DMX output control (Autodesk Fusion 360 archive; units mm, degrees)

design "case" references "3-D NC5FAH", "ptb6043-2010bp", "nac3mpxxa", "xiaodmx", "5V2AACDC"
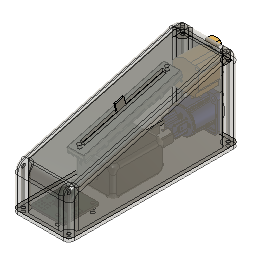
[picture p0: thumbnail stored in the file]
sketch "Sketch1" plane through (0, 0, 0) normal (0, 0, 1) x axis (1, 0, 0)
  line L1 (-25.2326, 75) -> (24.7674, 75)
  line L2 (-25.2326, -75) -> (-25.2326, 75)
  line L3 (24.7674, -75) -> (-25.2326, -75)
  line L4 (24.7674, 75) -> (24.7674, -75)
  line L5 (-25.2326, -75) -> (24.7674, 75)
  line L6 (24.7674, -75) -> (-25.2326, 75)
  point P6 (-0.2326, 0)
  point P4 (-25.2326, -75)
  point P5 (24.7674, -75)
  point P3 (-25.2326, 75)
  horizontal L1
  perpendicular L1 L2
  parallel L1 L3
  parallel L2 L4
  coincident L5 P6
  coincident L6 P6
  dimension "d1" distance P4 P5 = 50
  dimension "d2" distance P3 P4 = 150
extrude "Extrude1" new body sketch "Sketch1" profile of L1 L2 L3 L4 along normal blind 75
chamfer "Chamfer1" distance 150 Rotate Angle 15
fillet "Fillet1" radius 10 10
fillet "Fillet2" radius 5
sketch "Sketch2" plane through (0, -13.726, 51.226) normal (0, -0.2588, 0.9659) x axis (1, 0, 0)
  line L1 (19.7674, 78.8236) -> (19.7674, -55.7623)
  line L2 (-20.2326, 78.8236) -> (19.7674, 78.8236)
  line L3 (-20.2326, -55.7623) -> (-20.2326, 78.8236)
  line L4 (19.7674, -55.7623) -> (-20.2326, -55.7623)
  line L5 (19.7674, -55.7623) -> (-20.2326, 78.8236)
  line L6 (-20.2326, -55.7623) -> (19.7674, 78.8236)
  point P4 (-20.2326, 78.8236)
  point P6 (-20.2326, 78.8236)
  point P2 (19.7674, -55.7623)
  point P7 (19.7674, -55.7623)
  point P3 (19.7674, 78.8236)
  point P8 (19.7674, 78.8236)
  point P5 (-20.2326, -55.7623)
  point P9 (-20.2326, -55.7623)
  point P10 (-0.2326, 11.5307)
  coincident P4 P6
  coincident P2 P7
  coincident P3 P8
  coincident P5 P9
  midpoint L6 P10
shell "Shell1" innerThickness 3
component_from_bodies "ボディ -> コンポーネント"
component_insert "Component Insert1"
joint "Assemble" alignAngle 90 alignOffsetX 0 alignOffsetY 0 alignOffsetZ 0
sketch "Sketch3" plane through (0.2736, -1.8193, 51.3105) normal (0, -0.2588, 0.9659) x axis (-1, 0, 0)
  line L1 (-6.3438, -43.7578) -> (-6.3438, -43.5578)
  line L2 (7.3562, -43.7578) -> (-6.3438, -43.7578)
  line L3 (7.3562, -43.5578) -> (7.3562, -43.7578)
  line L4 (7.5562, -43.5578) -> (7.3562, -43.5578)
  line L5 (7.5562, 43.5422) -> (7.5562, -43.5578)
  line L6 (7.3562, 43.5422) -> (7.5562, 43.5422)
  line L7 (7.3562, 43.7422) -> (7.3562, 43.5422)
  line L8 (-6.3438, 43.7422) -> (7.3562, 43.7422)
  line L9 (-6.3438, 43.5422) -> (-6.3438, 43.7422)
  line L10 (-6.5438, 43.5422) -> (-6.3438, 43.5422)
  line L11 (-6.5438, -43.5578) -> (-6.5438, 43.5422)
  line L12 (-6.3438, -43.5578) -> (-6.5438, -43.5578)
  line L13 (-0.9188, -37.0078) -> (1.9312, -37.0078)
  line L14 (-0.9188, 36.9922) -> (-0.9188, -37.0078)
  line L15 (1.9312, 36.9922) -> (-0.9188, 36.9922)
  line L16 (1.9312, -37.0078) -> (1.9312, 36.9922)
  line L17 (1.9312, -37.0078) -> (-0.9188, 36.9922)
  line L18 (-0.9188, -37.0078) -> (1.9312, 36.9922)
  line L19 (-0.9188, -37.0078) -> (1.9312, -37.0078)
  line L20 (-0.9188, 36.9922) -> (1.9312, 36.9922)
  line L21 (-0.9188, -37.0078) -> (-0.9188, 36.9922)
  line L22 (1.9312, 36.9922) -> (1.9312, -37.0078)
  circle C1 centre (0.5062, -40.0078) radius 1.25
  circle C2 centre (0.5062, 39.9922) radius 1.25
  circle C3 centre (0.5062, -40.0078) radius 1.5
  circle C4 centre (0.5062, 39.9922) radius 1.5
  point P18 (-0.9188, 36.9922)
  point P20 (-0.9188, 36.9922)
  point P16 (1.9312, -37.0078)
  point P21 (1.9312, -37.0078)
  point P19 (1.9312, 36.9922)
  point P22 (1.9312, 36.9922)
  point P17 (-0.9188, -37.0078)
  point P23 (-0.9188, -37.0078)
  point P24 (0.5062, -0.0078)
  coincident P18 P20
  coincident P16 P21
  coincident P19 P22
  coincident P17 P23
  coincident L18 P24
  coincident L17 P24
  concentric C1 C3
  concentric C2 C4
  dimension "d22" diameter C3 = 3
  dimension "d23" diameter C4 = 3
extrude "Extrude1" cut sketch "Sketch3" profile of C1 C2 L13 L14 L15 L16 L17 L18 L19 L20 L21 L22 C3 C4 along normal blind 10
component_insert "Component Insert2"
step "GeometricRelationship1"
step "GeometricRelationship2" Offset 0
component_insert "Component Insert3"
step "GeometricRelationship3"
step "GeometricRelationship4" Offset 0
position "Position1"
sketch "Sketch6" plane through (0, 66.1549, 0) normal (0, -1, 0) x axis (1, 0, 0)
  line L1 (31, -12.7756) -> (-9, -12.7756)
  line L2 (31, 49.1922) -> (31, -12.7756)
  line L3 (-9, 49.1922) -> (31, 49.1922)
  line L4 (-9, -12.7756) -> (-9, 49.1922)
  circle C1 centre (11, 3.8312) radius 12
  circle C2 centre (11, 3.8312) radius 11.509
  circle C3 centre (20.5, 15.8312) radius 1.5
  circle C4 centre (20.5, 15.8312) radius 1.7227
  circle C5 centre (1.5, -8.1688) radius 1.5
  circle C6 centre (1.5, -8.1688) radius 1.7227
  circle C7 centre (11, 36.1664) radius 11.1
  arc A1 centre (11, 36.1664) radius 9.75 clockwise from (13.5, 45.5904) to (8.5, 45.5904)
  circle C8 centre (20.9, 46.0664) radius 1.5
  circle C9 centre (20.9, 46.0664) radius 1.175
  circle C10 centre (1.1, 26.2664) radius 1.5
  circle C11 centre (1.1, 26.2664) radius 1.175
  concentric C1 C2
  concentric C3 C4
  concentric C5 C6
  concentric C7 A1
  concentric C8 C9
  concentric C10 C11
  dimension "d28" diameter C1 = 24
  dimension "d29" diameter C3 = 3
  dimension "d30" diameter C5 = 3
  dimension "d31" diameter C7 = 22.2
  dimension "d32" diameter C8 = 3
  dimension "d33" diameter C10 = 3
extrude "Extrude2" cut sketch "Sketch6" profile of C1 C2 C3 C5 C7 C8 C9 C10 C11 against normal blind 60
sketch "Sketch7" plane through (0, 0, -12.7756) normal (0, 0, -1) x axis (1, 0, 0)
  line L1 (33, -64.1549) -> (33, 75.8451)
  line L2 (-9, -66.1549) -> (31, -66.1549)
  line L3 (-11, 75.8451) -> (-11, -64.1549)
  line L4 (31, 77.8451) -> (-9, 77.8451)
  line L5 (36, 75.8451) -> (36, -64.1549)
  line L6 (-9, 80.8451) -> (31, 80.8451)
  line L7 (-14, -64.1549) -> (-14, 75.8451)
  line L8 (31, -69.1549) -> (-9, -69.1549)
  line L9 (-9, 75.8451) -> (-12.5355, 79.3806)
  line L10 (31, 75.8451) -> (34.5355, 79.3806)
  line L11 (31, -64.1549) -> (34.5355, -67.6905)
  line L12 (-9, -64.1549) -> (-12.5355, -67.6905)
  arc A1 centre (31, -64.1549) radius 2 clockwise from (33, -64.1549) to (31, -66.1549)
  arc A2 centre (-9, -64.1549) radius 2 clockwise from (-9, -66.1549) to (-11, -64.1549)
  arc A3 centre (-9, 75.8451) radius 2 clockwise from (-11, 75.8451) to (-9, 77.8451)
  arc A4 centre (31, 75.8451) radius 2 clockwise from (31, 77.8451) to (33, 75.8451)
  arc A5 centre (31, -64.1549) radius 5 clockwise from (36, -64.1549) to (31, -69.1549)
  arc A6 centre (31, 75.8451) radius 5 clockwise from (31, 80.8451) to (36, 75.8451)
  arc A7 centre (-9, 75.8451) radius 5 clockwise from (-14, 75.8451) to (-9, 80.8451)
  arc A8 centre (-9, -64.1549) radius 5 clockwise from (-9, -69.1549) to (-14, -64.1549)
  circle C1 centre (-9, 75.8451) radius 1.2
  circle C2 centre (31, 75.8451) radius 1.2
  circle C3 centre (-9, -64.1549) radius 1.2
  circle C4 centre (31, -64.1549) radius 1.2
  circle C5 centre (-9, 75.8451) radius 5
  circle C6 centre (31, 75.8451) radius 5
  circle C7 centre (31, -64.1549) radius 5
  circle C8 centre (-9, -64.1549) radius 5
  point P22 (-12.5355, 79.3806)
  point P11 (-9, 75.8451)
  point P23 (-9, 75.8451)
  point P24 (34.5355, 79.3806)
  point P13 (31, 75.8451)
  point P25 (31, 75.8451)
  point P26 (34.5355, -67.6905)
  point P5 (31, -64.1549)
  point P27 (31, -64.1549)
  point P28 (-12.5355, -67.6905)
  point P8 (-9, -64.1549)
  point P29 (-9, -64.1549)
  point P30 (-9, 75.8451)
  point P33 (31, -64.1549)
  point P34 (-9, 75.8451)
  point P35 (31, 75.8451)
  point P36 (31, -64.1549)
  midpoint A7 P22
  coincident P11 P23
  midpoint A6 P24
  coincident P13 P25
  midpoint A5 P26
  coincident P5 P27
  midpoint A8 P28
  coincident P8 P29
  coincident P23 P30
  concentric A4 C2
  concentric A2 C3
  coincident P27 P33
  coincident P23 P34
  coincident P22 C5
  coincident P25 P35
  coincident P27 P36
  coincident P26 C7
  concentric C3 C8
  coincident P28 C8
  dimension "d38" diameter C1 = 2.4
  dimension "d39" diameter C2 = 2.4
  dimension "d40" diameter C3 = 2.4
  dimension "d41" diameter C4 = 2.4
extrude "Extrude3" add sketch "Sketch7" profile of L1 L3 A3 L4 A4 C1 C2 C5 C6 to an object
extrude "Extrude6" add sketch "Sketch7" profile of L1 A1 L2 A2 L3 C3 C4 C7 C8 against normal blind 61.9
fillet "Fillet2" radius 1.8 1.8
extrude "Extrude4" new body of existing geometry blind 7.2
copy_paste_bodies "CutPasteBodies"
component_insert "Component Insert4"
component_insert "Component Insert5"
sketch "Sketch8" plane through (0, 0, -12.7756) normal (0, 0, -1) x axis (1, 0, 0)
  line L1 (33, -57.3579) -> (33, 69.048)
  line L2 (-2.2029, -66.1549) -> (24.2029, -66.1549)
  line L3 (-11, 69.048) -> (-11, -57.3579)
  line L4 (24.2029, 77.8451) -> (-2.2029, 77.8451)
  line L5 (36, 75.8451) -> (36, -64.1549)
  line L6 (-9, 80.8451) -> (31, 80.8451)
  line L7 (-14, -64.1549) -> (-14, 75.8451)
  line L8 (31, -69.1549) -> (-9, -69.1549)
  circle C1 centre (31, -64.1549) radius 1.2
  circle C2 centre (-9, -64.1549) radius 1.2
  circle C3 centre (-9, 75.8451) radius 1.2
  circle C4 centre (31, 75.8451) radius 1.2
  arc A1 centre (31.2, -57.3579) radius 1.8 clockwise from (33, -57.3579) to (31.1471, -59.1571)
  arc A2 centre (31, -64.1549) radius 5 clockwise from (26.0022, -64.302) to (31.1471, -59.1571)
  arc A3 centre (24.2029, -64.3549) radius 1.8 clockwise from (26.0022, -64.302) to (24.2029, -66.1549)
  arc A4 centre (-2.2029, -64.3549) radius 1.8 clockwise from (-2.2029, -66.1549) to (-4.0022, -64.302)
  arc A5 centre (-9, -64.1549) radius 5 clockwise from (-9.1471, -59.1571) to (-4.0022, -64.302)
  arc A6 centre (-9.2, -57.3579) radius 1.8 clockwise from (-9.1471, -59.1571) to (-11, -57.3579)
  arc A7 centre (-9.2, 69.048) radius 1.8 clockwise from (-11, 69.048) to (-9.1471, 70.8472)
  arc A8 centre (-9, 75.8451) radius 5 clockwise from (-4.0022, 75.9921) to (-9.1471, 70.8472)
  arc A9 centre (-2.2029, 76.0451) radius 1.8 clockwise from (-4.0022, 75.9921) to (-2.2029, 77.8451)
  arc A10 centre (24.2029, 76.0451) radius 1.8 clockwise from (24.2029, 77.8451) to (26.0022, 75.9921)
  arc A11 centre (31, 75.8451) radius 5 clockwise from (31.1471, 70.8472) to (26.0022, 75.9921)
  arc A12 centre (31.2, 69.048) radius 1.8 clockwise from (31.1471, 70.8472) to (33, 69.048)
  arc A13 centre (31, -64.1549) radius 5 clockwise from (36, -64.1549) to (31, -69.1549)
  arc A14 centre (31, 75.8451) radius 5 clockwise from (31, 80.8451) to (36, 75.8451)
  arc A15 centre (-9, 75.8451) radius 5 clockwise from (-14, 75.8451) to (-9, 80.8451)
  arc A16 centre (-9, -64.1549) radius 5 clockwise from (-9, -69.1549) to (-14, -64.1549)
extrude "Extrude7" new body sketch "Sketch8" along normal blind 3
sketch "Sketch9" plane through (0, 0, -8.44) normal (0, 0, 1) x axis (-1, 0, 0)
  line L1 (-25.3494, 73.1672) -> (-25.3469, 73.3101)
  line L2 (-25.3494, 45.1886) -> (-25.3494, 73.1672)
  line L3 (-25.3469, 45.0457) -> (-25.3494, 45.1886)
  line L4 (-23.3494, 43.1886) -> (-23.4923, 43.1911)
  line L5 (1.6828, 43.1886) -> (-23.3494, 43.1886)
  line L6 (1.8257, 43.1911) -> (1.6828, 43.1886)
  line L7 (3.6828, 45.1886) -> (3.6803, 45.0457)
  line L8 (3.6828, 73.1672) -> (3.6828, 45.1886)
  line L9 (3.6803, 73.3101) -> (3.6828, 73.1672)
  line L10 (1.6828, 75.1672) -> (1.8257, 75.1647)
  line L11 (-23.3494, 75.1672) -> (1.6828, 75.1672)
  line L12 (-23.4923, 75.1647) -> (-23.3494, 75.1672)
  arc A1 centre (-23.3494, 73.1672) radius 2.0026 clockwise from (-25.3469, 73.3101) to (-23.4923, 75.1647)
  arc A2 centre (-23.3494, 45.1886) radius 2.0026 clockwise from (-23.4923, 43.1911) to (-25.3469, 45.0457)
  arc A3 centre (1.6828, 45.1886) radius 2.0026 clockwise from (3.6803, 45.0457) to (1.8257, 43.1911)
  arc A4 centre (1.6828, 73.1672) radius 2.0026 clockwise from (1.8257, 75.1647) to (3.6803, 73.3101)
  circle C1 centre (-22.276, 46.262) radius 1.5875
  circle C2 centre (0.584, 46.262) radius 1.5875
  circle C3 centre (-11.058, 47.85) radius 0.3374
  circle C4 centre (-4.75, 47.85) radius 0.3374
  circle C5 centre (-11.058, 49.85) radius 0.3374
  circle C6 centre (-4.75, 49.85) radius 0.3374
  circle C7 centre (1.6, 51.406) radius 0.3374
  circle C8 centre (-11.058, 51.85) radius 0.3374
  circle C9 centre (-4.75, 51.85) radius 0.3374
  circle C10 centre (1.6, 53.406) radius 0.3374
  circle C11 centre (1.6, 55.406) radius 0.3374
  circle C12 centre (-23.8, 56.93) radius 0.4874
  circle C13 centre (-21.26, 56.93) radius 0.4874
  circle C14 centre (-6.02, 56.93) radius 0.4874
  circle C15 centre (-3.48, 56.93) radius 0.4874
  circle C16 centre (-17.44, 56.92) radius 0.3874
  circle C17 centre (-9.82, 56.92) radius 0.3874
  circle C18 centre (-23.8, 59.47) radius 0.4874
  circle C19 centre (-21.26, 59.47) radius 0.4874
  circle C20 centre (-6.02, 59.47) radius 0.4874
  circle C21 centre (-3.48, 59.47) radius 0.4874
  circle C22 centre (-17.44, 59.46) radius 0.3874
  circle C23 centre (-9.82, 59.46) radius 0.3874
  circle C24 centre (1.6, 60.232) radius 0.4874
  circle C25 centre (-23.8, 62.01) radius 0.4874
  circle C26 centre (-21.26, 62.01) radius 0.4874
  circle C27 centre (-6.02, 62.01) radius 0.4874
  circle C28 centre (-3.48, 62.01) radius 0.4874
  circle C29 centre (-17.44, 62) radius 0.3874
  circle C30 centre (-9.82, 62) radius 0.3874
  circle C31 centre (1.6, 62.772) radius 0.4874
  circle C32 centre (-23.8, 64.55) radius 0.4874
  circle C33 centre (-21.26, 64.55) radius 0.4874
  circle C34 centre (-6.02, 64.55) radius 0.4874
  circle C35 centre (-3.48, 64.55) radius 0.4874
  circle C36 centre (-17.44, 64.54) radius 0.3874
  circle C37 centre (-9.82, 64.54) radius 0.3874
  circle C38 centre (-0.94, 67.066) radius 0.4874
  circle C39 centre (1.6, 67.066) radius 0.4874
  circle C40 centre (-23.8, 67.09) radius 0.4874
  circle C41 centre (-21.26, 67.09) radius 0.4874
  circle C42 centre (-6.02, 67.09) radius 0.4874
  circle C43 centre (-3.48, 67.09) radius 0.4874
  circle C44 centre (-0.94, 69.606) radius 0.4874
  circle C45 centre (1.6, 69.606) radius 0.4874
  circle C46 centre (-23.8, 69.63) radius 0.4874
  circle C47 centre (-21.26, 69.63) radius 0.4874
  circle C48 centre (-6.02, 69.63) radius 0.4874
  circle C49 centre (-3.48, 69.63) radius 0.4874
  circle C50 centre (-16.18, 70.9) radius 1.5875
  circle C51 centre (-0.94, 72.146) radius 0.4874
  circle C52 centre (1.6, 72.146) radius 0.4874
  circle C53 centre (-23.8, 72.17) radius 0.4874
  circle C54 centre (-21.26, 72.17) radius 0.4874
  circle C55 centre (-6.02, 72.17) radius 0.4874
  circle C56 centre (-3.48, 72.17) radius 0.4874
  point P22 (-22.276, 46.262)
  point P23 (0.584, 46.262)
  point P71 (-16.18, 70.9)
  dimension "d68" angle P22 P23 P71 = 76.103
extrude "Extrude8" cut sketch "Sketch9" profile of C1 C2 C50 against normal blind 10
sketch "Sketch10" plane through (0, 0, -12.7756) normal (0, 0, 1) x axis (-1, 0, 0)
  line L1 (9, -69.1549) -> (-31, -69.1549)
  line L2 (14, 75.8451) -> (14, -64.1549)
  line L3 (-31, 80.8451) -> (9, 80.8451)
  line L4 (-36, -64.1549) -> (-36, 75.8451)
  arc A1 centre (9, -64.1549) radius 5 clockwise from (14, -64.1549) to (9, -69.1549)
  arc A2 centre (9, 75.8451) radius 5 clockwise from (9, 80.8451) to (14, 75.8451)
  arc A3 centre (-31, 75.8451) radius 5 clockwise from (-36, 75.8451) to (-31, 80.8451)
  arc A4 centre (-31, -64.1549) radius 5 clockwise from (-31, -69.1549) to (-36, -64.1549)
  circle C1 centre (-31, -64.1549) radius 1.2
  circle C2 centre (-31, 75.8451) radius 1.2
  circle C3 centre (9, -64.1549) radius 1.2
  circle C4 centre (9, 75.8451) radius 1.2
  circle C5 centre (-16.18, 70.9) radius 1.5875
  circle C6 centre (-22.276, 46.262) radius 1.5875
  circle C7 centre (0.584, 46.262) radius 1.5875
  circle C8 centre (9, -64.1549) radius 1.5
  circle C9 centre (-31, -64.1549) radius 1.5
  circle C10 centre (9, 75.8451) radius 1.5
  circle C11 centre (-31, 75.8451) radius 1.5
  concentric A1 C8
  concentric A4 C9
  concentric A2 C10
  concentric A3 C11
  dimension "d69" diameter C8 = 3
  dimension "d70" diameter C9 = 3
  dimension "d71" diameter C10 = 3
  dimension "d72" diameter C11 = 3
extrude "Extrude9" cut sketch "Sketch10" profile of C1 C2 C3 C4 C8 C9 C10 C11 against normal blind 10
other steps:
base_feature "基準フィーチャ"
base_feature "Base Feature"
create_component "CreateComponent3"
reparent_decal "デカールを再ペアレント化"
remove_body "RemoveBody2"
joint_origin "JointOrigin2"
reparent_decal "ReparentDecal3"
remove_body "RemoveBody3"
reparent_decal "ReparentDecal4"
remove_body "RemoveBody4"

design "5V2AACDC"
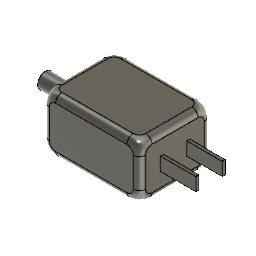
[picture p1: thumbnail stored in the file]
sketch "Sketch1" plane through (0, 0, 0) normal (0, 0, 1) x axis (1, 0, 0)
  line L1 (-23, 17) -> (23, 17)
  line L2 (-23, -17) -> (-23, 17)
  line L3 (23, -17) -> (-23, -17)
  line L4 (23, 17) -> (23, -17)
  line L5 (-23, -17) -> (23, 17)
  line L6 (23, -17) -> (-23, 17)
  point P6 (0, 0)
  point P1 (0, 0)
  point P4 (-23, -17)
  point P5 (23, -17)
  point P3 (-23, 17)
  horizontal L1
  perpendicular L1 L2
  parallel L1 L3
  parallel L2 L4
  coincident L5 P6
  coincident L6 P6
  coincident P1 P6
  dimension "d3" distance P4 P5 = 46
  dimension "d4" distance P3 P4 = 34
extrude "Extrude1" new body sketch "Sketch1" profile of L1 L2 L3 L4 along normal blind 26
sketch "Sketch2" plane through (-23, 0, 0) normal (-1, 0, 0) x axis (0, -1, 0)
  line L1 (17, 0) -> (-17, 0)
  line L2 (17, 26) -> (17, 0)
  line L3 (-17, 26) -> (17, 26)
  line L4 (-17, 0) -> (-17, 26)
  circle C1 centre (0, 13) radius 3.75
  dimension "d5" diameter C1 = 7.5
extrude "Extrude2" add sketch "Sketch2" profile of C1 along normal blind 16
sketch "Sketch3" plane through (23, 0, 0) normal (1, 0, 0) x axis (0, 1, 0)
  line L1 (17, 0) -> (-17, 0)
  line L2 (17, 26) -> (17, 0)
  line L3 (-17, 26) -> (17, 26)
  line L4 (-17, 0) -> (-17, 26)
  line L5 (-7.05, 16.175) -> (7.05, 16.175)
  line L6 (-7.05, 9.825) -> (-7.05, 16.175)
  line L7 (7.05, 9.825) -> (-7.05, 9.825)
  line L8 (7.05, 16.175) -> (7.05, 9.825)
  line L9 (-7.05, 9.825) -> (7.05, 16.175)
  line L10 (7.05, 9.825) -> (-7.05, 16.175)
  line L11 (-5.55, 16.175) -> (-7.05, 16.175)
  line L12 (-5.55, 9.825) -> (-5.55, 16.175)
  line L13 (-7.05, 9.825) -> (-5.55, 9.825)
  line L14 (-7.05, 16.175) -> (-7.05, 9.825)
  line L15 (5.55, 16.175) -> (7.05, 16.175)
  line L16 (5.55, 9.825) -> (5.55, 16.175)
  line L17 (7.05, 9.825) -> (5.55, 9.825)
  line L18 (7.05, 16.175) -> (7.05, 9.825)
  point P10 (0, 13)
  point P8 (-7.05, 9.825)
  point P9 (7.05, 9.825)
  point P7 (-7.05, 16.175)
  point P11 (-5.55, 16.175)
  point P6 (7.05, 16.175)
  point P14 (5.55, 16.175)
  horizontal L5
  perpendicular L5 L6
  parallel L5 L7
  parallel L6 L8
  coincident L9 P10
  coincident L10 P10
  horizontal L11
  vertical L12
  horizontal L13
  vertical L14
  horizontal L15
  vertical L16
  horizontal L17
  vertical L18
  dimension "d8" distance P8 P9 = 14.1
  dimension "d9" distance P7 P8 = 6.35
  dimension "d10" distance P7 P11 = 1.5
  dimension "d11" distance P6 P14 = 1.5
extrude "Extrude3" add sketch "Sketch3" profile of L11 L12 L13 L14 L15 L16 L17 L18 along normal blind 17
fillet "Fillet1" radius 3

design "ptb6043-2010bp"
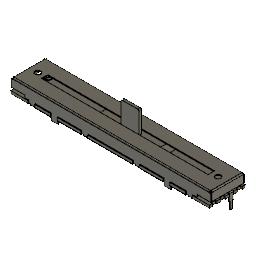
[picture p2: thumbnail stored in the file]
description: Part Number
part number: PTB6043-2010BP
base_feature "Base Feature"
move "Move1" RotateAngle 90

design "3-D NC5FAH"
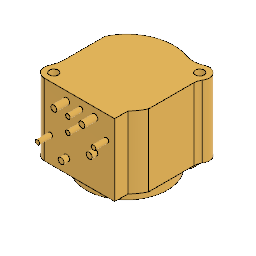
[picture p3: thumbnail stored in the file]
description: Part Number
part number: D-NC5FAH
base_feature "Base Feature"

design "nac3mpxxa"
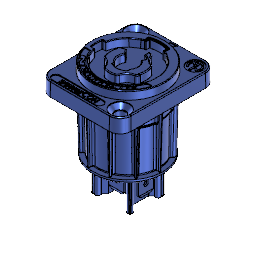
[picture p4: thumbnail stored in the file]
description: Part Number
part number: NAC3MPXXA
base_feature "Base Feature"

design "xiaodmx"
description: KiCad electronic assembly
part number: xiaodmx 1
description: Part Number
part number: xiaodmx 1.2.1
part number: xiaodmx 1.2.2
part number: PinHeader-01x07_P2.54mm_Vertical_THT
part number: xiaodmx 1.5.1
part number: xiaodmx 1.5.2
part number: PinHeader-01x02_P2.54mm_Vertical_THT
part number: xiaodmx 1.6.1
part number: xiaodmx 1.6.2
part number: xiaodmx 1.6.3
base_feature "Base Feature1"
base_feature "Base Feature1"
base_feature "Base Feature1"
base_feature "Base Feature1"
base_feature "Base Feature1"
base_feature "Base Feature1"
base_feature "Base Feature1"
base_feature "Base Feature1"
base_feature "Base Feature1"
base_feature "Base Feature1"
base_feature "Base Feature1"
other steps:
create_component "CreateComponent1"
create_component "CreateComponent2"
create_component "CreateComponent1"
create_component "CreateComponent2"
create_component "CreateComponent3"
create_component "CreateComponent1"
create_component "CreateComponent2"
create_component "CreateComponent4"
create_component "CreateComponent1"
create_component "CreateComponent2"
create_component "CreateComponent3"
create_component "CreateComponent5"
create_component "CreateComponent6"
create_component "CreateComponent7"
